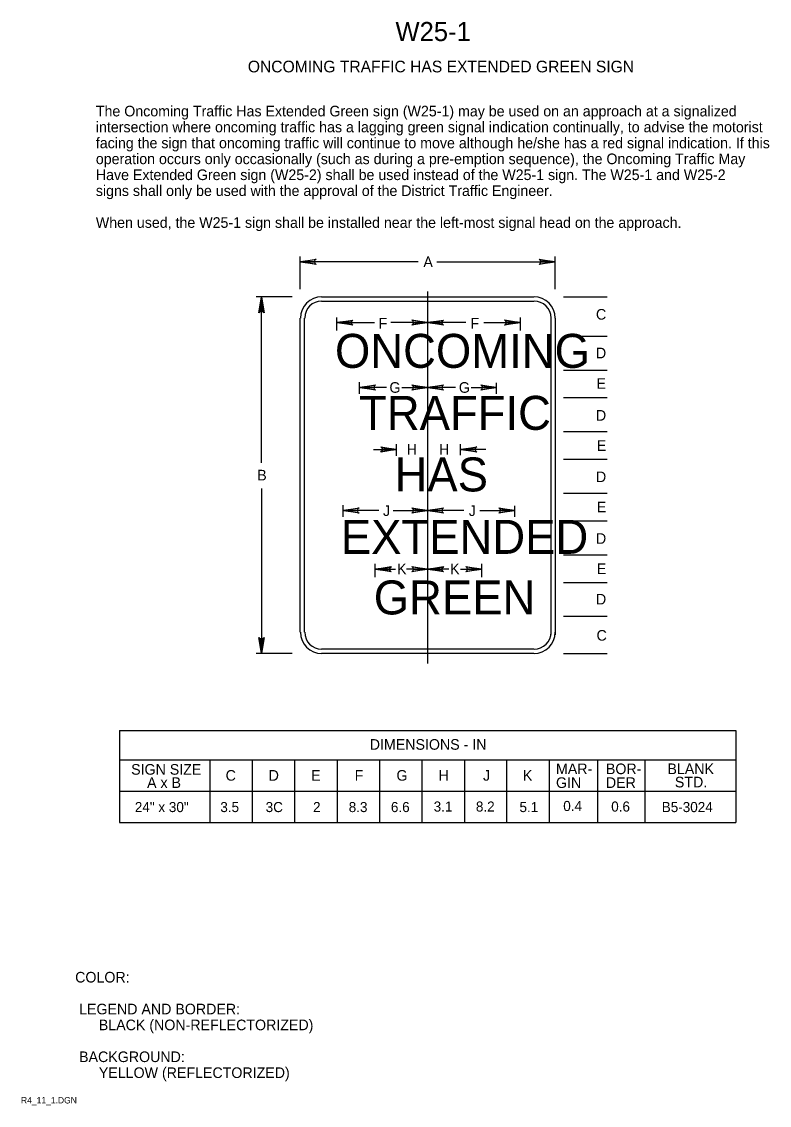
# Model space of a CAD drawing. Extents: x 0.013 to 0.189, y 0.004 to 0.259.
import ezdxf

# ---------------------------------------------------------------- set-up
doc = ezdxf.new("R2010")
doc.units = 0
for name, color, linetype in [('1', 7, 'Continuous'), ('11', 7, 'Continuous'), ('12', 7, 'Continuous'), ('2', 7, 'Continuous'), ('3', 7, 'Continuous')]:
    doc.layers.add(name, color=color, linetype=linetype)

# ---------------------------------------------------------------- blocks, each defined once
blk = doc.blocks.new('RARROW')
at = {"layer": '3'}
for p, q in [((-2.156, 0.285), (-2.2665, 0.384625)), ((-2.2665, 0.384625), (0, 0)), ((0, 0), (-2.2665, -0.379125)), ((-2.156, 0.285), (-2.075625, 0.12075)), ((0, 0), (-2.156, 0.285)), ((-2.14975, -0.2705), (0, 0)), ((-2.075625, 0.12075), (0, 0)), ((0, 0), (-2.074, -0.108)), ((-2.2665, -0.379125), (-2.14975, -0.2705)), ((-2.074, -0.108), (-2.14975, -0.2705))]:
    blk.add_line(p, q, dxfattribs=at)

msp = doc.modelspace()

# ---------------------------------------------------------------- linework, layer by layer
at = {"layer": '11'}
for p, q in [((0.08313, 0.19438), (0.13312, 0.19438)), ((0.07812, 0.11538), (0.07812, 0.18938)), ((0.13812, 0.18938), (0.13812, 0.11474)), ((0.13312, 0.11038), (0.08313, 0.11038))]:
    msp.add_line(p, q, dxfattribs=at)
for centre, start, end in [((0.08317, 0.18938), 90, 180), ((0.13317, 0.18938), 0, 90), ((0.08317, 0.11538), 180, 270), ((0.13317, 0.11538), 270, 0)]:
    msp.add_arc(centre, 0.005, start, end, dxfattribs=at)
at = {"layer": '3'}
for p, q in [((0.07812, 0.19615), (0.07812, 0.20388)), ((0.10587, 0.20263), (0.07812, 0.20263)), ((0.11025, 0.20263), (0.13812, 0.20263)), ((0.13812, 0.19615), (0.13812, 0.20388)), ((0.07625, 0.19438), (0.06775, 0.19438)), ((0.069, 0.15531), (0.069, 0.19438)), ((0.10812, 0.19563), (0.10812, 0.108)), ((0.14012, 0.19438), (0.15038, 0.19438)), ((0.08313, 0.19338), (0.13312, 0.19338)), ((0.07912, 0.11538), (0.07912, 0.18938)), ((0.08676, 0.18643), (0.08676, 0.18955)), ((0.10812, 0.18967), (0.10812, 0.18705)), ((0.10812, 0.1883), (0.11188, 0.18892)), ((0.11188, 0.18892), (0.11168, 0.18874)), ((0.12642, 0.18876), (0.12624, 0.18893)), ((0.12624, 0.18893), (0.12999, 0.1883)), ((0.12999, 0.18643), (0.12999, 0.18955)), ((0.13712, 0.18938), (0.13712, 0.11481)), ((0.08681, 0.1883), (0.09557, 0.1883)), ((0.10877, 0.1883), (0.09946, 0.1883)), ((0.11168, 0.18874), (0.10812, 0.1883)), ((0.10812, 0.1883), (0.11156, 0.18847)), ((0.11313, 0.1883), (0.10812, 0.1883)), ((0.11156, 0.1881), (0.10812, 0.1883)), ((0.10812, 0.1883), (0.11169, 0.18783)), ((0.11188, 0.18767), (0.10812, 0.1883)), ((0.11712, 0.1883), (0.10812, 0.1883)), ((0.11156, 0.18847), (0.11168, 0.18874)), ((0.11169, 0.18783), (0.11156, 0.1881)), ((0.11169, 0.18783), (0.11188, 0.18767)), ((0.12136, 0.1883), (0.12999, 0.1883)), ((0.12999, 0.1883), (0.12624, 0.18768)), ((0.12624, 0.18768), (0.12643, 0.18785)), ((0.12642, 0.18876), (0.12656, 0.18849)), ((0.12999, 0.1883), (0.12642, 0.18876)), ((0.12643, 0.18785), (0.12999, 0.1883)), ((0.12656, 0.18812), (0.12643, 0.18785)), ((0.12656, 0.18849), (0.12999, 0.1883)), ((0.12999, 0.1883), (0.12656, 0.18812)), ((0.14012, 0.18513), (0.15038, 0.18513)), ((0.14012, 0.17713), (0.15038, 0.17713)), ((0.0921, 0.17153), (0.0921, 0.17428)), ((0.10812, 0.17503), (0.10812, 0.17178)), ((0.12437, 0.17151), (0.12437, 0.17413)), ((0.0984, 0.17303), (0.09253, 0.17303)), ((0.10201, 0.17303), (0.10812, 0.17303)), ((0.11467, 0.17303), (0.10867, 0.17303)), ((0.11837, 0.17303), (0.12418, 0.17303)), ((0.14012, 0.17063), (0.15038, 0.17063)), ((0.14012, 0.16263), (0.15038, 0.16263)), ((0.09536, 0.15845), (0.10082, 0.15845)), ((0.10082, 0.15695), (0.10082, 0.1597)), ((0.10812, 0.15983), (0.10812, 0.15721)), ((0.11589, 0.15708), (0.11589, 0.1597)), ((0.12185, 0.15845), (0.11665, 0.15845)), ((0.14012, 0.15613), (0.15038, 0.15613)), ((0.069, 0.14924), (0.069, 0.11038)), ((0.14012, 0.14813), (0.15038, 0.14813)), ((0.10812, 0.14601), (0.10812, 0.14276)), ((0.08822, 0.14256), (0.08822, 0.14531)), ((0.09664, 0.14406), (0.08865, 0.14406)), ((0.10003, 0.14406), (0.10812, 0.14406)), ((0.11665, 0.14406), (0.10867, 0.14406)), ((0.12039, 0.14406), (0.12842, 0.14406)), ((0.12861, 0.14254), (0.12861, 0.14517)), ((0.14012, 0.14163), (0.15038, 0.14163)), ((0.14012, 0.13363), (0.15038, 0.13363)), ((0.09579, 0.12836), (0.09579, 0.13147)), ((0.09579, 0.13022), (0.10059, 0.13022)), ((0.10877, 0.13022), (0.10318, 0.13022)), ((0.10812, 0.1316), (0.10812, 0.12897)), ((0.10812, 0.13022), (0.11188, 0.13084)), ((0.11168, 0.13066), (0.10812, 0.13022)), ((0.10812, 0.13022), (0.11156, 0.1304)), ((0.11156, 0.13002), (0.10812, 0.13022)), ((0.10812, 0.13022), (0.11169, 0.12975)), ((0.11188, 0.12959), (0.10812, 0.13022)), ((0.11279, 0.13022), (0.10812, 0.13022)), ((0.11307, 0.13022), (0.10812, 0.13022)), ((0.11156, 0.1304), (0.11168, 0.13066)), ((0.11188, 0.13084), (0.11168, 0.13066)), ((0.11586, 0.13022), (0.12085, 0.13022)), ((0.11729, 0.13069), (0.1171, 0.13085)), ((0.1171, 0.13085), (0.12085, 0.13022)), ((0.12085, 0.13022), (0.1171, 0.1296)), ((0.11729, 0.13069), (0.11742, 0.13042)), ((0.12085, 0.13022), (0.11729, 0.13069)), ((0.1173, 0.12978), (0.12085, 0.13022)), ((0.11742, 0.13042), (0.12085, 0.13022)), ((0.12085, 0.13022), (0.11742, 0.13004)), ((0.12085, 0.12836), (0.12085, 0.13147)), ((0.11169, 0.12975), (0.11156, 0.13002)), ((0.11169, 0.12975), (0.11188, 0.12959)), ((0.1171, 0.1296), (0.1173, 0.12978)), ((0.11742, 0.13004), (0.1173, 0.12978)), ((0.14012, 0.12713), (0.15038, 0.12713)), ((0.14012, 0.11913), (0.15038, 0.11913)), ((0.07625, 0.11038), (0.06775, 0.11038)), ((0.13312, 0.11138), (0.08313, 0.11138)), ((0.14012, 0.11038), (0.15038, 0.11038)), ((0.03556, 0.0922), (0.03556, 0.07057)), ((0.03556, 0.0922), (0.18069, 0.0922)), ((0.18069, 0.0922), (0.18069, 0.07057)), ((0.03556, 0.08532), (0.15671, 0.08532)), ((0.05686, 0.08532), (0.05686, 0.07057)), ((0.06681, 0.08532), (0.06681, 0.07057)), ((0.07681, 0.08532), (0.07681, 0.07057)), ((0.08681, 0.08532), (0.08681, 0.07057)), ((0.09681, 0.08532), (0.09681, 0.07057)), ((0.10677, 0.08532), (0.10677, 0.07057)), ((0.1168, 0.08532), (0.1168, 0.07057)), ((0.12672, 0.08532), (0.12672, 0.07057)), ((0.13676, 0.08532), (0.13676, 0.07057)), ((0.14814, 0.08532), (0.14814, 0.07057)), ((0.15671, 0.08532), (0.18069, 0.08532)), ((0.15926, 0.08532), (0.15926, 0.07057)), ((0.03556, 0.07795), (0.15671, 0.07795)), ((0.15671, 0.07795), (0.18069, 0.07795)), ((0.03556, 0.07057), (0.15671, 0.07057)), ((0.15671, 0.07057), (0.18069, 0.07057))]:
    msp.add_line(p, q, dxfattribs=at)
for centre, start, end in [((0.08317, 0.18938), 90, 180), ((0.13317, 0.18938), 0, 90), ((0.08317, 0.11538), 180, 270), ((0.13317, 0.11538), 270, 0)]:
    msp.add_arc(centre, 0.004, start, end, dxfattribs=at)

# ---------------------------------------------------------------- block references
at = {"layer": '3', "xscale": 0.0016545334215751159, "yscale": 0.0016366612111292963}
for p, rotation in [((0.07812, 0.20263), 180), ((0.069, 0.19438), 90), ((0.08676, 0.1883), 180), ((0.0921, 0.17303), 180), ((0.10812, 0.17303), 180), ((0.11594, 0.15845), 180), ((0.08822, 0.14406), 180), ((0.10812, 0.14406), 180), ((0.09579, 0.13022), 180), ((0.069, 0.11038), -90)]:
    msp.add_blockref('RARROW', p, dxfattribs=dict(at, rotation=rotation))
for p in [(0.13812, 0.20263), (0.10812, 0.1883), (0.10812, 0.17303), (0.12437, 0.17303), (0.10082, 0.15845), (0.10812, 0.14406), (0.12862, 0.14406), (0.10812, 0.13022)]:
    msp.add_blockref('RARROW', p, dxfattribs=at)

# ---------------------------------------------------------------- texts
at = {"layer": '1'}
for s, height, p in [('W25-1', 0.0045, (0.10055, 0.25462)), ('ONCOMING TRAFFIC HAS EXTENDED GREEN SIGN', 0.0027503, (0.06579, 0.24725)), ('COLOR:', 0.0025, (0.02513, 0.03287)), (' LEGEND AND BORDER:', 0.0024998, (0.02513, 0.02537)), ('      BLACK (NON-REFLECTORIZED)', 0.0024998, (0.02513, 0.02163)), (' BACKGROUND:', 0.0024998, (0.02513, 0.01413)), ('      YELLOW (REFLECTORIZED)', 0.0024998, (0.02513, 0.01038)), ('R4_11_1.DGN', 0.0015, (0.01238, 0.00438))]:
    msp.add_text(s, height=height, dxfattribs=at).set_placement(p)
at = {"layer": '12'}
for s, p in [('ONCOMING', (0.0863, 0.17765)), ('TRAFFIC', (0.09198, 0.16305)), ('HAS', (0.10033, 0.14854)), ('EXTENDED', (0.08768, 0.13384)), ('GREEN', (0.09543, 0.11957))]:
    msp.add_text(s, height=0.008, dxfattribs=at).set_placement(p)
at = {"layer": '2'}
for s, height, p in [('The Oncoming Traffic Has Extended Green sign (W25-1) may be used on an approach at a signalized ', 0.0024998, (0.03, 0.23688)), ('intersection where oncoming traffic has a lagging green signal indication continually, to advise the motorist ', 0.00249975, (0.03, 0.23313)), ('facing the sign that oncoming traffic will continue to move although he/she has a red signal indication. If this ', 0.00249975, (0.03, 0.22938)), ('operation occurs only occasionally (such as during a pre-emption sequence), the Oncoming Traffic May ', 0.00249975, (0.03, 0.22563)), ('Have Extended Green sign (W25-2) shall be used instead of the W25-1 sign. The W25-1 and W25-2 ', 0.0024998, (0.03, 0.22188)), ('signs shall only be used with the approval of the District Traffic Engineer.', 0.0024998, (0.03, 0.21813)), ('When used, the W25-1 sign shall be installed near the left-most signal head on the approach.', 0.0024998, (0.03, 0.21063))]:
    msp.add_text(s, height=height, dxfattribs=at).set_placement(p)
at = {"layer": '3'}
for s, height, p in [('A', 0.0025, (0.10712, 0.20138)), ('C', 0.0025, (0.14775, 0.18901)), ('F', 0.0025, (0.09658, 0.18692)), ('F', 0.0025, (0.1182, 0.18692)), ('D', 0.0025, (0.14775, 0.1799)), ('G', 0.0025, (0.09912, 0.17178)), ('G', 0.0025, (0.11547, 0.17178)), ('E', 0.0025, (0.14788, 0.17271)), ('D', 0.0025, (0.14775, 0.16521)), ('H', 0.0025, (0.10319, 0.1572)), ('H', 0.0025, (0.1108, 0.1572)), ('E', 0.0025, (0.14795, 0.1581)), ('B', 0.0025, (0.068, 0.15113)), ('D', 0.0025, (0.14775, 0.15073)), ('E', 0.0025, (0.14795, 0.14362)), ('J', 0.0025, (0.09761, 0.14276)), ('J', 0.0025, (0.1178, 0.14276)), ('D', 0.0025, (0.14775, 0.1362)), ('K', 0.0025, (0.10091, 0.12904)), ('K', 0.0025, (0.1134, 0.12904)), ('E', 0.0025, (0.14795, 0.12909)), ('D', 0.0025, (0.14775, 0.12191)), ('C', 0.0025, (0.14789, 0.11339)), ('DIMENSIONS - IN', 0.0024998, (0.09449, 0.0877)), ('SIGN SIZE', 0.0025, (0.03831, 0.08182)), ('MAR-', 0.0025, (0.13834, 0.08195)), ('BOR-', 0.0025, (0.15009, 0.08195)), ('BLANK', 0.0025, (0.16458, 0.08196)), ('C', 0.0025, (0.06056, 0.08041)), ('D', 0.0025, (0.07069, 0.08041)), ('E', 0.0025, (0.08069, 0.08041)), ('F', 0.0025, (0.09094, 0.08041)), ('G', 0.0025, (0.10078, 0.08041)), ('H', 0.0025, (0.11067, 0.08041)), ('J', 0.0025, (0.12116, 0.08041)), ('K', 0.0025, (0.13054, 0.08041)), ('A x B', 0.0025, (0.04206, 0.0787)), ('GIN', 0.0025, (0.13834, 0.0787)), ('DER', 0.0025, (0.15009, 0.0787)), ('STD.', 0.0025, (0.16633, 0.07883)), ('24" x 30"', 0.002375, (0.03918, 0.07301)), ('3.5', 0.002375, (0.05931, 0.07301)), ('3C', 0.002375, (0.06998, 0.07301)), ('2', 0.00238, (0.08114, 0.07301)), ('8.3', 0.002375, (0.08954, 0.07301)), ('6.6', 0.002375, (0.09947, 0.07301)), ('3.1', 0.002375, (0.10954, 0.07313)), ('8.2', 0.002375, (0.11948, 0.07313)), ('5.1', 0.002375, (0.12974, 0.07301)), ('0.4', 0.002375, (0.14005, 0.07326)), ('0.6', 0.002375, (0.15134, 0.07313)), ('B5-3024', 0.002375, (0.16324, 0.07301))]:
    msp.add_text(s, height=height, dxfattribs=at).set_placement(p)

doc.saveas('drawing.dxf')
